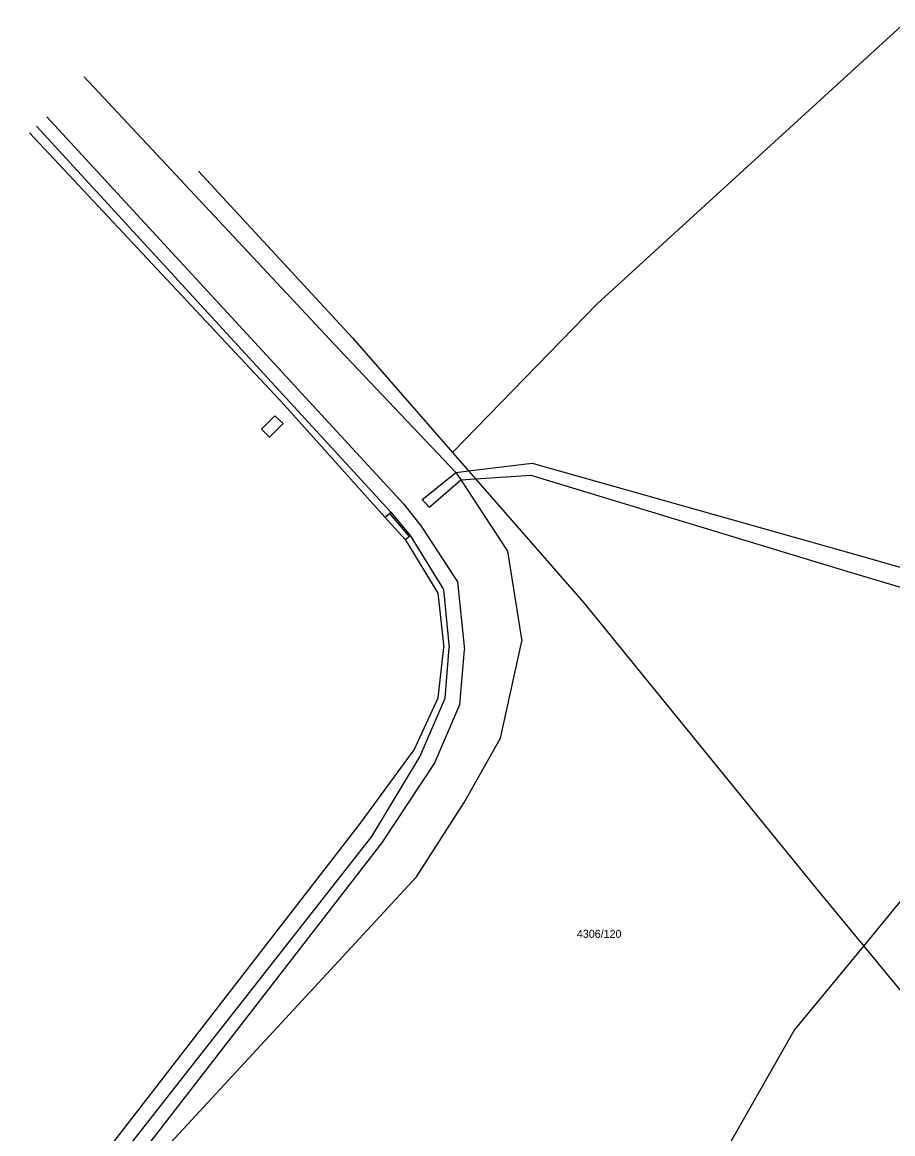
# Model space of a CAD drawing. Extents: x -717507 to -715515, y -957700 to -954941.
# Drawn here: x -716920.4 to -716735.3, y -956467.6 to -956231.4 of the extents above; entities that cross this region are included whole.
import ezdxf

# ---------------------------------------------------------------- set-up
doc = ezdxf.new("R2010")
doc.units = 0
for name, color, linetype in [('Hranice parcel', 7, 'Continuous'), ('Parcelní čísla', 7, 'Continuous'), ('Vnitřní kresba', 7, 'Continuous')]:
    doc.layers.add(name, color=color, linetype=linetype)

msp = doc.modelspace()

# ---------------------------------------------------------------- linework, layer by layer
at = {"layer": 'Hranice parcel'}
for points in [[(-716798.09, -956291.25), (-716732.53, -956231.41)], [(-716882.87, -956263.03), (-716850.14, -956298.45)], [(-716828.86, -956322.83), (-716798.09, -956291.25)], [(-716850.14, -956298.45), (-716828.86, -956322.83)], [(-716828.86, -956322.83), (-716825.46, -956326.73)], [(-716828.18, -956327.07), (-716825.46, -956326.73)], [(-716828.18, -956327.07), (-716827.14, -956328.62)], [(-716827.14, -956328.62), (-716817.17, -956343.82)], [(-716817.17, -956343.82), (-716814.15, -956362.96)], [(-716818.67, -956383.57), (-716814.15, -956362.96)], [(-716826.41, -956397.2), (-716818.67, -956383.57)], [(-716836.54, -956413), (-716826.41, -956397.2)], [(-716894.85, -956476.06), (-716836.54, -956413)], [(-716741.45, -956427.73), (-716729.56, -956413.32)], [(-716756.25, -956445.68), (-716741.45, -956427.73)], [(-716788.35, -956502.03), (-716756.25, -956445.68)]]:
    msp.add_lwpolyline(points, dxfattribs=at)
at = {"layer": 'Vnitřní kresba'}
for points in [[(-716907.16, -956243.03), (-716852.91, -956300.99)], [(-716915.15, -956251.49), (-716839.28, -956333.78)], [(-716918.82, -956254.93), (-716864.61, -956312.77)], [(-716917.35, -956253.53), (-716841.99, -956335.5)], [(-716852.91, -956300.99), (-716828.18, -956327.07)], [(-716864.61, -956312.77), (-716843.28, -956336.55)], [(-716869.52, -956317.87), (-716866.64, -956315.04)], [(-716867.79, -956319.57), (-716864.88, -956316.67)], [(-716866.64, -956315.04), (-716864.88, -956316.67)], [(-716869.52, -956317.87), (-716867.79, -956319.57)], [(-716825.46, -956326.73), (-716811.94, -956325.08)], [(-716811.94, -956325.08), (-716744.43, -956344.18)], [(-716834.44, -956332.13), (-716828.18, -956327.07)], [(-716833.05, -956333.8), (-716827.14, -956328.62)], [(-716827.14, -956328.62), (-716823.98, -956328.42)], [(-716825.46, -956326.73), (-716823.98, -956328.42)], [(-716823.98, -956328.42), (-716812.22, -956327.68)], [(-716823.98, -956328.42), (-716800.98, -956354.8)], [(-716812.22, -956327.68), (-716745.54, -956347.92)], [(-716835.3, -956332.79), (-716834.44, -956332.13)], [(-716835.3, -956332.79), (-716833.87, -956334.48)], [(-716843.28, -956336.55), (-716842.27, -956335.78)], [(-716842.27, -956335.78), (-716841.99, -956335.5)], [(-716842.27, -956335.78), (-716838.11, -956340.67)], [(-716841.99, -956335.5), (-716837.85, -956340.45)], [(-716839.28, -956333.78), (-716835.55, -956338.52)], [(-716833.87, -956334.48), (-716833.05, -956333.8)], [(-716843.28, -956336.55), (-716838.92, -956341.35)], [(-716838.92, -956341.35), (-716838.11, -956340.67)], [(-716838.11, -956340.67), (-716837.85, -956340.45)], [(-716837.85, -956340.45), (-716830.76, -956351.98)], [(-716835.55, -956338.52), (-716827.81, -956350.29)], [(-716838.92, -956341.35), (-716832.03, -956352.71)], [(-716744.43, -956344.18), (-716702.47, -956356.16)], [(-716745.54, -956347.92), (-716702.03, -956360.84)], [(-716830.76, -956351.98), (-716829.61, -956364.37)], [(-716827.81, -956350.29), (-716826.33, -956364.74)], [(-716832.03, -956352.71), (-716830.7, -956364.24)], [(-716800.98, -956354.8), (-716751.48, -956415.54)], [(-716831.93, -956374.99), (-716830.7, -956364.24)], [(-716830.43, -956375.06), (-716829.61, -956364.37)], [(-716827.31, -956376.4), (-716826.33, -956364.74)], [(-716837.01, -956385.99), (-716831.93, -956374.99)], [(-716835.81, -956387.54), (-716830.43, -956375.06)], [(-716832.69, -956388.89), (-716827.31, -956376.4)], [(-716848.46, -956401.61), (-716837.01, -956385.99)], [(-716846.05, -956404.4), (-716835.81, -956387.54)], [(-716843.93, -956405.82), (-716832.69, -956388.89)], [(-716908.87, -956479.65), (-716848.46, -956401.61)], [(-716932.64, -956514.75), (-716846.05, -956404.4)], [(-716912.39, -956494.22), (-716843.93, -956405.82)], [(-716751.48, -956415.54), (-716741.45, -956427.73)], [(-716741.45, -956427.73), (-716724.57, -956448.23)]]:
    msp.add_lwpolyline(points, dxfattribs=at)

# ---------------------------------------------------------------- texts
at = {"layer": 'Parcelní čísla'}
msp.add_text('4306/120', height=1.7, dxfattribs=at).set_placement((-716802.43, -956425.97))

doc.saveas('drawing.dxf')
